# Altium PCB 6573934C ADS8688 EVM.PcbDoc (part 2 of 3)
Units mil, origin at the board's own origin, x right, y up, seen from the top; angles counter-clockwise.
Board outline 4100 x 2700 mil, 6 copper layers (L1_Analog, L2_GND, L3_AnalogPower, L4_DigPower, L5_GND, L6_Digital), stack 58.4 mil thick; 282 components, 187 nets, 719 pads, 318 vias.
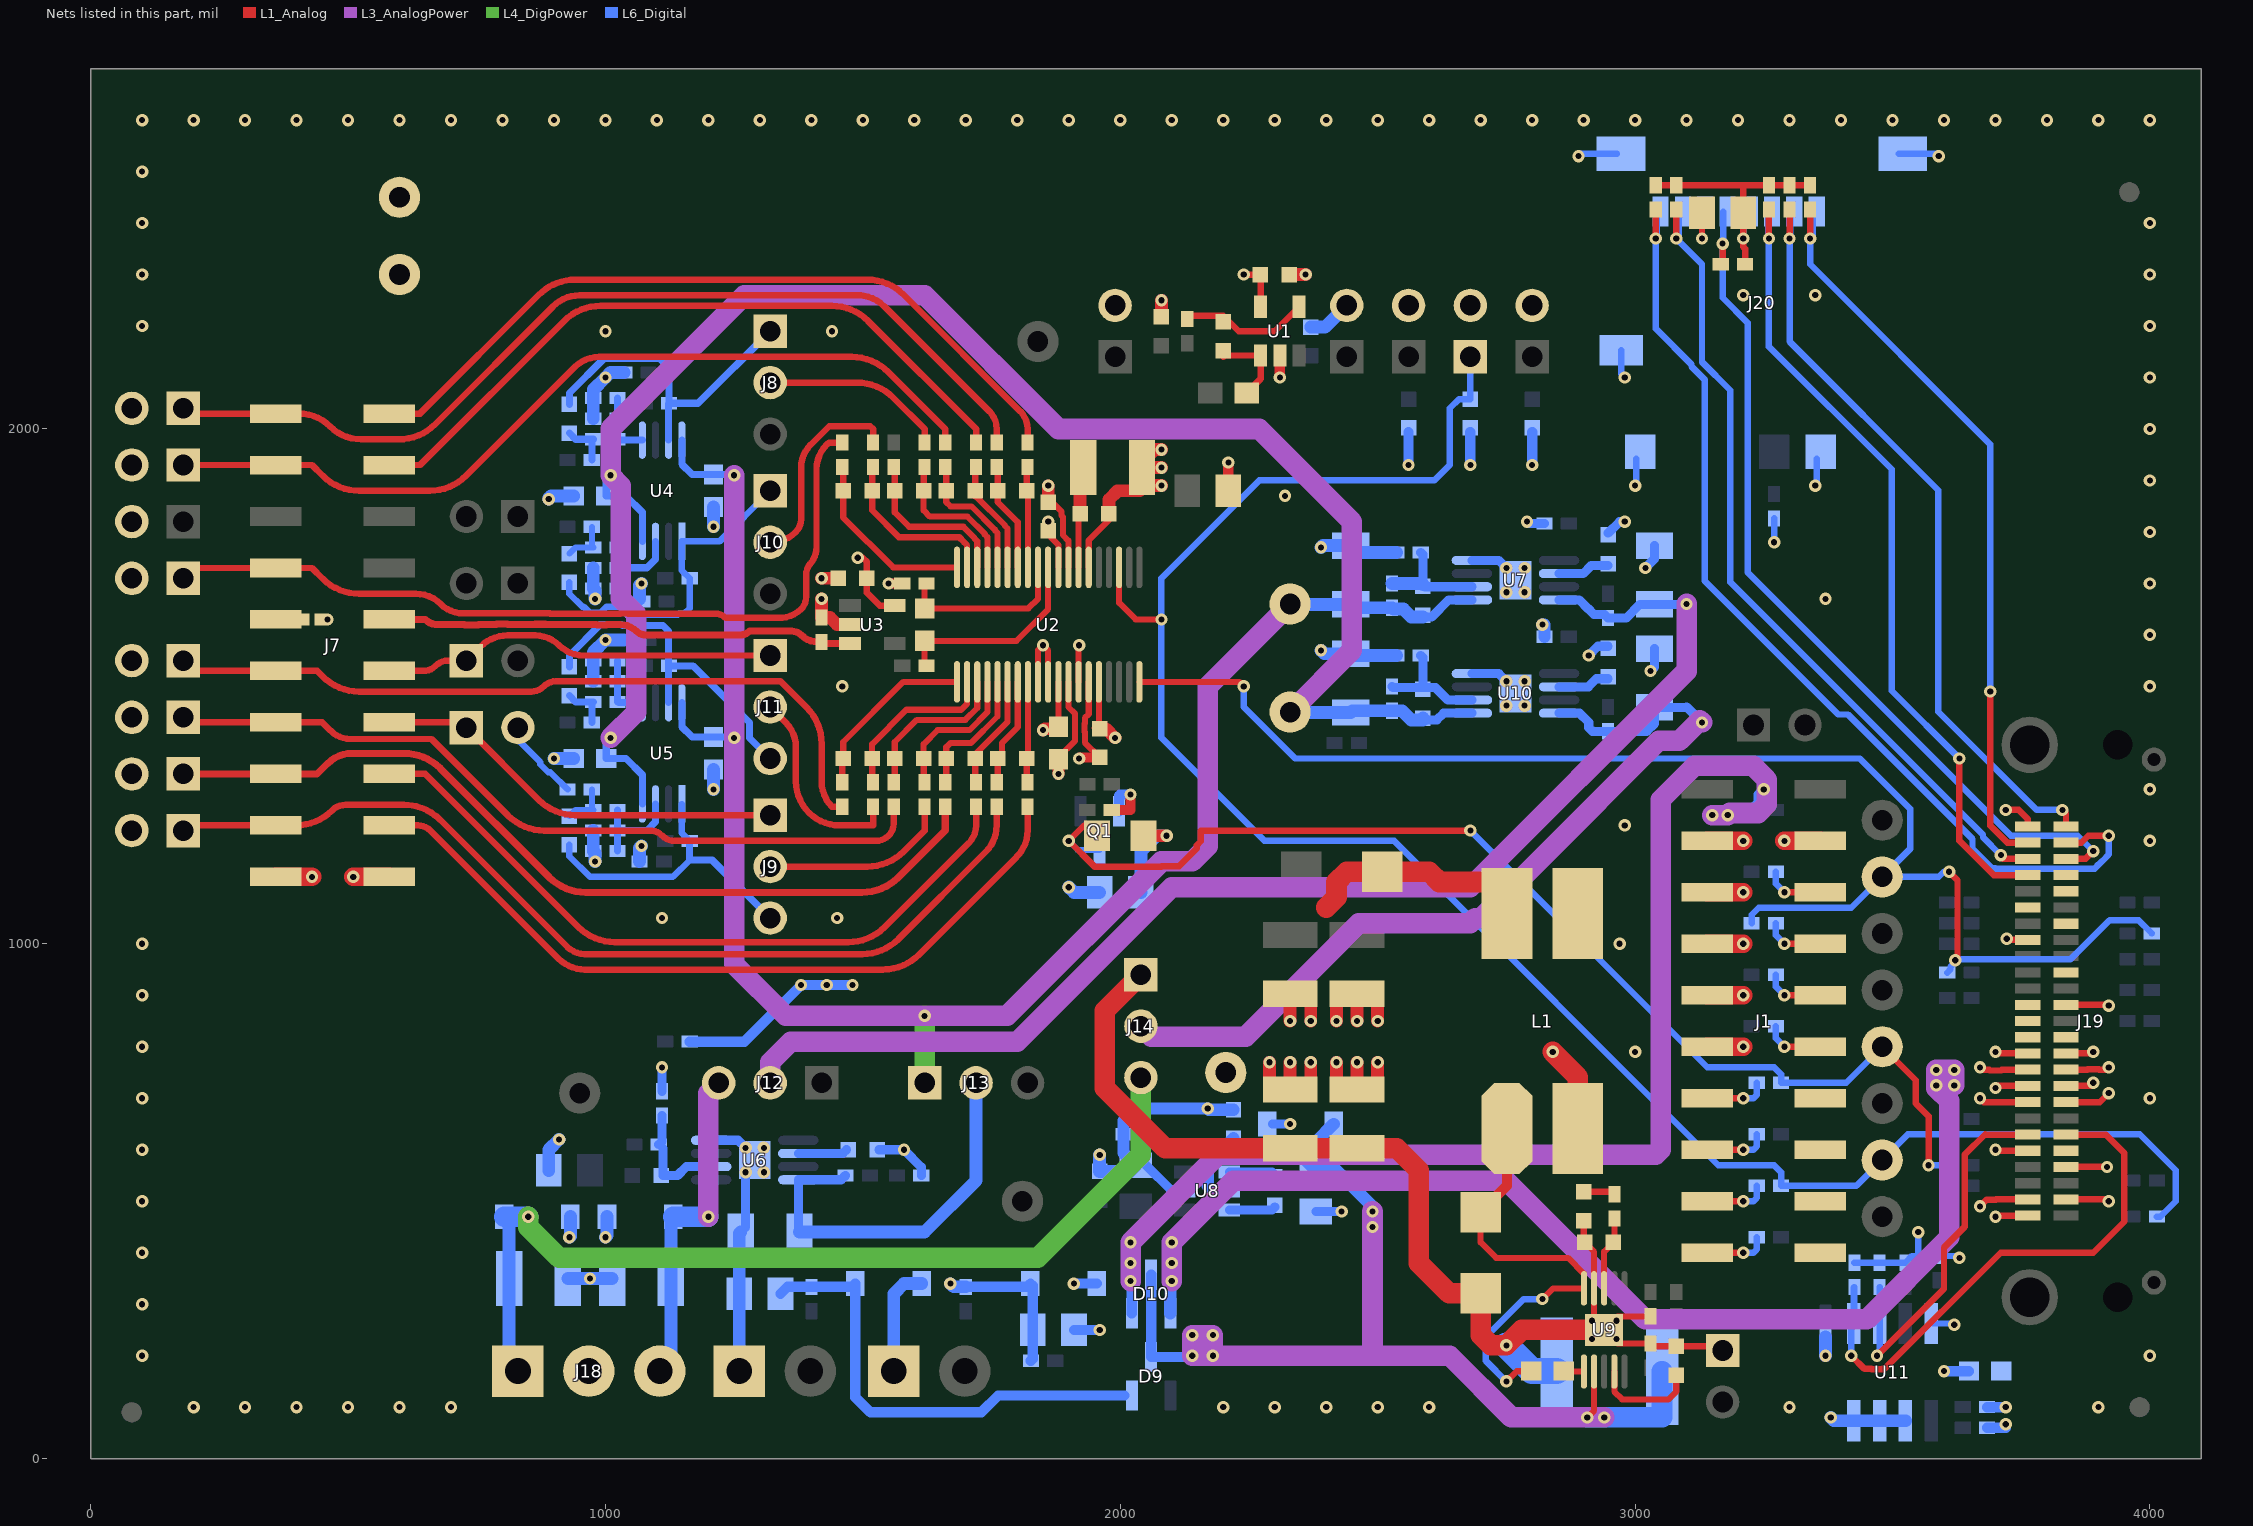
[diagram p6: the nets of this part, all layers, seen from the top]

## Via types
v1: diameter 24, hole 12, L1_Analog to L6_Digital, tented both sides, 318 vias

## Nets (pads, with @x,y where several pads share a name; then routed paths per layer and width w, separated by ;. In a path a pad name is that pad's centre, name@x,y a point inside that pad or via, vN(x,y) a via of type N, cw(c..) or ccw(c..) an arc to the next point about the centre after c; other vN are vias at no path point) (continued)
A1-: J7.7 J16.1 R40.1 | length 1605.9
  L1_Analog w12.52: J16.1@180,1710 200,1730 J7.7@360,1730 430,1730 450.71,1709.29 ccw(c521.42,1780) 521.42,1680 631.72,1680 cw(c631.72,1611.72) 680,1660 ccw(c723.99,1703.99) 723.99,1641.78 779.48,1641.78 779.55,1641.85 869.93,1641.85 ; 869.93,1641.78 892.02,1641.78 892.78,1641.02 1022.22,1641.02 1022.63,1641.44 1029.2,1641.44 1029.2,1641.58 1043.84,1641.58 1044.4,1641.02 1215.25,1641.02 cw(c1215.25,1618.39) 1220.69,1640.36 cw(c1215.25,1618.39) 1231.26,1634.39 ccw(c1238.44,1659.46) 1238.44,1633.39 1339.89,1633.39 ccw(c1339.89,1690.11) 1343.5,1633.5 ccw(c1339.89,1690.11) 1380,1650 ccw(c1355.86,1674.14) 1390,1674.14 1390,1717.09 cw(c1422.82,1717.09) 1396.07,1736.11 cw(c1422.82,1717.09) 1399.61,1740.29 ccw(c1358.79,1771.21) 1410,1771.21 1410,1921.72 cw(c1478.28,1921.72) 1430,1970 cw(c1438.74,1961.26) 1438.74,1973.62 R40.1@1460,1973.62
A2+: J7.12 J11.1 J30.1 | length 782.2
  L1_Analog w12.52: J7.12@580,1530 645.86,1530 ccw(c645.86,1564.14) 669.98,1539.98 ; 670.02,1540.02 cw(c694.14,1515.86) 694.14,1550 J30.1@730,1550 757.04,1577.04 cw(c810,1524.08) 810,1598.98 863.46,1598.98 cw(c863.46,1532.44) 910.51,1579.49 ccw(c957.56,1626.54) 957.56,1560 J11.1@1320,1560 ; J30.1@723.39,1536.61 J30.1@730,1530
A2-: J7.11 J26.1 R41.2 | length 1483.7
  L1_Analog w12.52: J26.1@180,1550 200,1530 J7.11@360,1530 440,1530 450.71,1519.29 ccw(c521.42,1590) 521.42,1490 855.86,1490 ccw(c855.86,1524.14) 880,1500 cw(c904.14,1475.86) 904.14,1510 1340,1510 1390.71,1459.29 cw(c1320,1388.58) 1420,1388.58 1420,1314.66 ccw(c1488.28,1314.66) 1440,1266.38 R41.2@1460,1266.38
A3+: J7.14 J9.1 J15.1 | length 810.3
  L1_Analog w12.52: J7.14@580,1430 720,1430 J15.1@730,1420 870.71,1279.29 ccw(c941.42,1350) 941.42,1250 J9.1@1320,1250
A3-: J7.13 J27.1 R35.2 | length 1521.5
  L1_Analog w12.52: J27.1@180,1440 190,1430 J7.13@360,1430 450,1430 466.07,1413.93 ccw(c504.86,1452.72) 504.86,1397.87 662.13,1397.87 810.71,1249.29 ccw(c881.42,1320) 881.42,1220 1085.86,1220 cw(c1085.86,1185.86) 1109.98,1210.02 ; 1110.02,1209.98 ccw(c1134.14,1234.14) 1134.14,1200 1525.86,1200 ccw(c1525.86,1234.14) 1550,1210 ccw(c1525.86,1234.14) 1560,1234.14 R35.2@1560,1266.38
A4+: J7.16 R28.2 | length 1406.6
  L1_Analog w12.52: J7.16@580,1330 650,1330 947.32,1032.68 ccw(c1018.04,1103.39) 1018.04,1003.39 1471.96,1003.39 ccw(c1471.96,1103.39) 1517.11,1014.16 ccw(c1471.96,1103.39) 1542.68,1032.68 1705.86,1195.86 ccw(c1671.72,1230) 1720,1230 R28.2@1720,1266.38
A4-: J7.15 J28.1 R30.2 | length 1688.6
  L1_Analog w13.78: J28.1@180,1330 J7.15@360,1330 440,1330 460,1350 cw(c508.28,1301.72) 508.28,1370 608.58,1370 cw(c608.58,1270) 679.29,1340.71 890.71,1129.29 ccw(c961.42,1200) 961.42,1100 1498.58,1100 ccw(c1498.58,1200) 1569.29,1129.29 1660,1220 R30.2@1660,1266.38
A5+: J7.18 R24.2 | length 1519.8
  L1_Analog w12.52: J7.18@580,1230 635.86,1230 cw(c635.86,1195.86) 660,1220 908.79,971.21 ccw(c960,1022.43) 960,950 1538.58,950 ccw(c1538.58,1050) 1550.74,950.74 ccw(c1538.58,1050) 1609.29,979.29 1798.79,1168.79 ccw(c1747.57,1220) 1820,1220 R24.2@1820,1266.38
A5-: J7.17 J29.1 R26.2 | length 1858.7
  L1_Analog w12.52: J29.1@180,1220 190,1230 J7.17@360,1230 398.58,1230 ccw(c398.58,1330) 469.29,1259.29 cw(c495.15,1233.43) 495.15,1270 608.58,1270 cw(c608.58,1170) 633.04,1266.96 cw(c608.58,1170) 679.29,1240.71 925.86,994.14 ccw(c960,1028.28) 960,980 1498.58,980 ccw(c1498.58,1080) 1569.29,1009.29 1738.79,1178.79 ccw(c1687.58,1230) 1760,1230 R26.2@1760,1266.38
A6+: J7.2 R23.1 | length 1495.2
  L1_Analog w12.52: J7.2@580,2030 640,2030 870.71,2260.71 cw(c941.42,2190) 897.83,2280 cw(c941.42,2190) 941.42,2290 1508.58,2290 cw(c1508.58,2190) 1579.29,2260.71 1805.86,2034.14 cw(c1771.72,2000) 1820,2000 R23.1@1820,1973.62
A6-: J7.1 J24.1 R25.1 | length 1847.4
  L1_Analog w12.52: J24.1@180,2040 190,2030 J7.1@360,2030 404.64,2030 cw(c404.64,1944.64) 464.96,2005.04 cw(c404.64,1944.64) 465,2005 ccw(c525.36,2065.36) 465.04,2004.96 ccw(c525.36,2065.36) 525.36,1980 598.58,1980 ccw(c598.58,2080) 669.29,2009.29 898.11,2238.11 ; 898.13,2238.13 cw(c950,2186.23) 950,2259.61 968.77,2259.61 969.36,2260.19 990.63,2260.19 990.63,2260.01 997.01,2260.01 997.41,2259.61 1227.26,2259.61 1432.59,2259.61 1432.99,2260.01 1439.37,2260.01 1439.37,2260.19 1460.64,2260.19 1461.23,2259.61 1490,2259.61 cw(c1490,2186.23) 1501.26,2258.74 cw(c1490,2186.23) 1541.89,2238.11 1745.86,2034.14 cw(c1711.72,2000) 1760,2000 R25.1@1760,1973.62
A7+: J7.4 R27.1 | length 1384.9
  L1_Analog w12.52: J7.4@580,1930 640,1930 919.92,2209.92 cw(c990.63,2139.21) 990.63,2239.21 1439.37,2239.21 cw(c1439.37,2139.21) 1510.08,2209.92 1720,2000 R27.1@1720,1973.62
A7-: J7.3 J23.1 R29.1 | length 1676.9
  L1_Analog w12.52: J23.1@180,1930 J7.3@360,1930 430,1930 450.71,1909.29 ccw(c521.42,1980) 521.42,1880 658.58,1880 ccw(c658.58,1980) 729.29,1909.29 940,2120 cw(c988.28,2071.72) 988.28,2140 1478.58,2140 cw(c1478.58,2040) 1549.29,2110.71 1660,2000 R29.1@1660,1973.62
A\L\M\: D1.1 Q1.3 R2.1 R86.2 TP8.1 | length 2325.3
  L1_Analog w11.81: v1(1900,1200) 1930,1230 D1.1@1955,1230
  L1_Analog w12.52: v1(1900,1200) 1950,1150 2080,1150 2080.99,1150.99 2114.44,1150.99 2149.01,1185.56 2149.01,1191.34 2156.63,1198.97 2156.63,1220 v1(2680,1220) ; TP8.1@3480,800 3545,735 3545,690 3570,665 v1(3570,570)
  L6_Digital w11.81: v1(1900,1200) 1917.4,1182.6 Q1.3@1960,1182.6
  L6_Digital w12.52: v1(2680,1220) 3140,760 3270,760 3283.62,746.38 R2.1@3283.62,730 3410,730 TP8.1@3480,800 ; v1(3570,570) R86.2@3606.38,570
AUX+: J7.10 R11.2 U3.3 | length 914.9
  L1_Analog w13.78: J7.10@580,1630 650,1630 ; 650.02,1629.98 ccw(c674.14,1654.14) 674.14,1620 725.93,1620 726.69,1619.24 746.54,1619.24 746.54,1619.59 753.11,1619.59 753.52,1620 787.43,1620 788.18,1620.76 788.26,1620.83 795.3,1620.83 810,1620.83 810,1620.41 816.57,1620.41 816.98,1620 851.29,1620 856.48,1620 856.89,1620.41 863.46,1620.41 863.46,1620.76 883.31,1620.76 884.07,1620 983.02,1620 983.43,1619.59 990,1619.59 ; 990,1619.55 1001.71,1619.55 1002.16,1620 1029.2,1620 cw(c1029.2,1576.45) 1060,1607.24 ccw(c1077.49,1624.73) 1077.49,1600 1262.51,1600 ccw(c1262.51,1624.73) 1280,1607.24 1362.51,1607.24 cw(c1362.51,1582.51) 1362.76,1607.24 cw(c1362.51,1582.51) 1380,1600 ccw(c1412.89,1632.89) 1412.89,1586.38 R11.2@1420,1586.38 1423.38,1583 U3.3@1475,1583
AUX-: J7.9 NT1.2 | length 49.9
  L1_Analog w12.52: J7.9@360,1630 J7.9@409.87,1630
AVDD: C1.1 C2.1 C10.2 C63.1 R77.1 TP16.1 U1.5 U2.9 U2.30 U3.5 | length 818.2
  L1_Analog w11.81: v1(1860,1820) C10.2@1860,1802 1860,1795 1869.09,1785.91 1869.09,1785.58 1879.69,1774.99 U2.9@1879.69,1731.22 ; U2.30@1879.69,1508.78 1879.69,1421.81 C63.1@1880,1421.5
  L1_Analog w12.52: v1(1490,1750) 1500,1750 1508,1742 C1.1@1508,1710 1508,1682 1533,1657 U3.5@1562,1657 ; v1(2240,2300) C2.1@2272,2300 2272.6,2299.4 U1.5@2272.6,2237.24
  L1_Analog w24: v1(1850,1415) 1853,1418 C63.1@1880,1418
  L6_Digital w20: R77.1@1163.62,810 1270,810 v1(1380,920) v1(1430,920) v1(1480,920)
C\S\: R7.1 R90.1 R103.2 TP7.1 U2.38 | length 2849.4
  L1_Analog w11.81: U2.38@2037.17,1508.78 2231.22,1508.78 v1(2240,1500)
  L1_Analog w12.52: v1(3610,1140) 3626.27,1123.73 3626.27,969.27 3625.32,968.32 v1@3622.27,968.32
  L3_AnalogPower w12.52: v1(3621.87,967.92) 3621.87,966.05 v1@3622.27,965.65 ; v1@3622.27,968.32 v1@3622.27,965.65 ; v1@3622.27,965.65 3622.27,965.27 3622.65,965.27 v1@3622.27,965.65
  L6_Digital w12.52: v1(2240,1500) 2240,1460 2340,1360 3436.56,1360 3534.13,1262.42 3534.13,1184.13 TP7.1@3480,1130 ; R7.1@3226.38,1040 3226.38,1056.38 3240,1070 3420,1070 TP7.1@3480,1130 ; R103.2@3606.38,944 3612.69,950.31 3612.69,955.31 3625.29,967.92 v1(3621.87,967.92) ; v1(3610,1140) 3600,1140 3590,1130 TP7.1@3480,1130 ; v1@3632.02,969.94 3845.72,969.94 3921.62,1045.84 3934.67,1045.84 3934.77,1045.95 3977.98,1045.95 4003.62,1020.3 R90.1@4003.62,1020
DAISY: J4.1 R8.1 R15.2 R89.1 TP3.1 U2.3 | length 3890.2
  L1_Analog w11.81: U2.3@1997.8,1731.22 1997.8,1662.2 2030,1630 v1(2080,1630)
  L6_Digital w12.52: J4.1@2680,2140 R15.2@2680,2058 2658,2058 2640,2040 2640,1930 2610,1900 2270,1900 2080,1710 v1(2080,1630) 2080,1400 2280,1200 2531.81,1200 3161.81,570 3270,570 3283.62,556.38 3283.62,530.3 R8.1@3283.62,530 3430,530 TP3.1@3480,580 3530,630 3980,630 4050,560 4050,500 4020,470 R89.1@4013.62,470
DVDD: C5.1 C61.1 C62.1 C64.1 D7.1 J20.4 R12.2 R13.1 R15.1 R18.1 R78.2 R79.2 R80.2 R81.2 R82.2 R83.2 R84.2 R85.2 R94.1 R95.1 R96.1 R102.1 R106.2 R108.2 TP17.1 U2.34 U11.8 | length 1617.4
  L1_Analog w11.81: C5.1@1950.43,1419.57 1958.43,1419.57 U2.34@1958.43,1508.78
  L1_Analog w12.52: R79.2@3040,2473.62 3210,2473.62 ; R81.2@3213.62,2320 3213.62,2350 3210,2353.62 v1(3210,2370) 3210,2473.62 ; R84.2@3340,2473.62 3210,2473.62
  L1_Analog w24: C5.1@1960,1418 1972,1418 v1(1990,1400)
  L6_Digital w12.52: v1(3210,2370) J20.4@3210,2425.12 ; v1(3270,1780) R85.2@3270,1826.38 ; R94.1@3426,380.62 R96.1@3525,380.62 3538,393.62 3550,393.62 v1(3550,440) ; U11.8@3575,262.5 3617.5,262.5 v1(3620,260) ; J20.4@3210,2425.12 3212.76,2422.36 3214.88,2422.36 3212.13,2425.12 J20.4@3210,2425.12
  L6_Digital w20: R106.2@1700,333.62 1819.15,333.62 D7.1@1825.53,340 1830,335.53 C61.1@1830,250 1830,193.62 R78.2@1826.38,190 ; v1(2560,1930) R18.1@2560,1994.22 ; v1(2680,1930) R15.1@2680,1994.22 ; v1(2800,1930) R13.1@2800,1994.22 ; v1(3600,170) C64.1@3648.5,170 ; R102.1@3683.62,100 v1(3720,100)
  L6_Digital w24: v1(1670,340) 1676.38,333.62 R106.2@1700,333.62
  L6_Digital w25: v1(1900,1110) 1910,1100 R12.2@1960,1100 ; v1(3370,200) R108.2@3370,236.38
EVM_ID_SCL: J19.12 R95.2 U11.6 | length 735.6
  L1_Analog w12.52: v1(3470,200) 3600,330 3600,410 3640,450 3640,590 3680,630 3680.47,629.53 J19.12@3762.99,629.53
  L6_Digital w12.52: v1(3470,200) 3475,205 U11.6@3475,262.5 R95.2@3475,333.38
EVM_ID_SDA: J19.11 R94.2 U11.5 | length 1119.5
  L1_Analog w12.52: v1(3420,200) 3445.78,174.22 3458.82,174.22 3459.17,173.87 3480.83,173.87 3481.18,174.22 3484.22,174.22 3710,400 3890,400 3950,460 3950,593.67 3914.15,629.53 J19.11@3837.01,629.53
  L6_Digital w12.52: v1(3420,200) U11.5@3420,257.5 ; U11.5@3425,262.5 3425,332.38 R94.2@3426,333.38 U11.5@3426,263.5
EVMSDCLK: J19.45 J20.5 R81.1 | length 1720.2
  L1_Analog w12.52: R81.1@3166.38,2320 3170,2320 v1(3170,2360) ; J19.45@3837.01,1164.96 3874.96,1164.96 v1(3890,1180)
  L6_Digital w12.52: J20.5@3171.58,2422.36 3171.58,2371.57 3170,2370 v1(3170,2360) 3170,2255 3218.46,2206.54 3218.46,1721.54 3730,1210 3860,1210 v1(3890,1180)
EVMSDCMD: J19.44 J20.3 R82.1 | length 1583.3
  L1_Analog w12.52: v1(3260,2370) R82.1@3260,2416.38 ; v1(3630,1360) 3630,1200 3696.54,1133.46 J19.44@3762.99,1133.46
  L6_Digital w12.52: J20.3@3258.19,2422.36 3258.19,2371.81 v1(3260,2370) 3260,2160 3498.46,1921.54 3498.46,1491.54 v1(3630,1360)
EVMSDDATA0: J19.46 J20.7 R80.1 | length 1627.2
  L1_Analog w12.52: v1(3080,2370) R80.1@3080,2426.38 ; v1(3710.45,1172.31) 3710.45,1170.45 3710,1170 3715.04,1164.96 J19.46@3762.99,1164.96
  L6_Digital w12.52: J20.7@3084.96,2422.36 3084.96,2374.96 v1(3080,2370) 3130,2320 3130,2130 3185,2075 3185,1702.68 3675.79,1211.89 3675.79,1206.97 v1(3710.45,1172.31)
EVMSDDATA1: J19.47 J20.8 R79.1 | length 1978.8
  L1_Analog w12.52: v1(3040,2370) R79.1@3040,2426.38 ; J19.47@3837.01,1196.46 3866.46,1196.46 3880,1210 v1(3920,1210)
  L6_Digital w12.52: J20.8@3041.65,2422.36 3041.65,2371.65 v1(3040,2370) 3040,2195 3109.61,2125.39 3109.61,2121.55 3135,2096.16 3135,1705 3394.61,1445.39 3413.45,1445.39 3655.39,1203.45 3655.39,1186.55 3654.42,1185.58 3693.47,1146.53 3699.27,1146.53 3699.63,1146.17 3892.63,1146.17 3900.32,1153.87 3900.82,1153.87 3916.13,1169.18 3916.13,1169.68 3920,1173.54 v1(3920,1210)
EVMSDDATA2: J19.48 J20.1 R84.1 | length 1482.8
  L1_Analog w12.52: v1(3340,2370) R84.1@3340,2426.38 ; v1(3690,1490) 3690,1229.72 3723.26,1196.46 J19.48@3762.99,1196.46
  L6_Digital w12.52: J20.1@3344.8,2422.36 3344.8,2374.8 v1(3340,2370) 3340,2320 3690,1970 v1(3690,1490)
EVMSDDATA3: J19.49 J20.2 R83.1 | length 1493.1
  L1_Analog w12.52: v1(3300,2370) R83.1@3300,2416.38 ; v1(3830,1260) 3837.01,1252.99 J19.49@3837.01,1227.95
  L6_Digital w12.52: J20.2@3301.5,2422.36 3301.5,2371.5 v1(3300,2370) 3300,2170 3589.02,1880.98 3589.02,1450.98 3780,1260 v1(3830,1260)
EXT_5V: C55.1 D5.1 D9.2 R69.2 | length 922.5
  L6_Digital w20: C55.1@1340,320 1353.62,333.62 R69.2@1400,333.62 1479.15,333.62 D5.1@1485.53,340 1485.53,119.19 1514.72,90 1730,90 1762.6,122.6 2007.8,122.6
EXT_HVDD: C59.2 D6.1 J12.3 J18.3 | length 647.2
  L3_AnalogPower w40: v1(1200,470) 1200,710 J12.3@1220,730
  L6_Digital w25: J18.3@1105.59,170 1127.09,191.5 1127.09,465.07 D6.1@1132.01,470
  L6_Digital w40: D6.1@1132.01,470 v1(1200,470)
EXT_HVSS: C60.1 D8.2 J14.3 J18.1 | length 1825.7
  L4_DigPower w40: v1(850,470) 850,450 910,390 1840,390 2040,590 J14.3@2040,740
  L6_Digital w25: D8.2@803.14,470 812.91,460.22 812.91,187.09 J18.1@830,170
  L6_Digital w40: D8.2@803.14,470 v1(850,470)
GND: C1.2 C2.2 C3.2 C5.2 C6.2 C7.2 C8.1 C9.1 C10.1 C16.1 C23.2 C24.1 C25.2 C26.2 C29.2 C30.2 C31.2 C32.2 C33.2 C34.2 C35.2 C36.2 C37.2 C40.2 C41.2 C43.2 C44.2 C46.2 C47.2 C49.1 C50.1 C53.2 C54.2 C55.2 C58.2 C59.1 C60.2 C61.2 C62.2 C63.2 C64.2 D3.2 D5.2 D6.2 D7.2 D8.1 J1.4 J2.2 J3.2 J4.2 J5.2 J6.2 J7.19 J7.20 J16.2 J18.2 J19.2 J19.4 J19.10 J19.16 J19.50 J20.0 J20.6 J22.2 J23.2 J24.2 J26.2 J27.2 J28.2 J29.2 J32.1 J33.1 L1.2 L1.3 NT1.1 Q1.2 R11.1 R14.1 R20.1 R21.1 R22.1 R36.1 R44.1 R48.2 R52.2 R57.2 R59.1 R62.2 R64.1 R65.2 R73.1 R74.1 R75.1 R76.1 R97.2 R104.2 TP11.1 U1.2 U2.6 U2.8 U2.28 U2.29 U2.31 U2.32 U2.33 U3.2 U6.4 U6.9 U7.4 U7.9 U8.2 U10.4 U10.9 U11.2 U11.3 U11.4 | length 7074.5
  L1_Analog w11.81: U2.28@1840.32,1508.78 1840.32,1570.32 v1(1850,1580) 1860,1570 U2.29@1860,1508.78 ; C10.1@1860,1858 1863,1855 1870.68,1855 1885.78,1839.9 1885.78,1832.22 1888.78,1829.22 1888.78,1793.73 1899.37,1783.14 U2.8@1899.37,1731.22 ; C63.2@1880,1362 1912.48,1394.48 1912.48,1446.89 1899.37,1460 U2.31@1899.37,1508.78 ; U2.32@1919.06,1508.78 1919.06,1579.06 v1(1920,1580) ; U2.33@1938.74,1508.78 1938.74,1446.23 1931.22,1438.71 1931.22,1428.21 1930.74,1427.73 1930.74,1411.42 1931.22,1410.94 1931.22,1390.78 C5.2@1960,1362 ; U2.6@1938.74,1731.22 1938.74,1783.74 1978,1823 C9.1@1978,1835
  L1_Analog w12.52: v1(3130,2370) C62.2@3130,2420 ; v1(3670,490) 3683.24,503.24 3701.09,503.24 3701.39,503.54 J19.4@3762.99,503.54 ; v1(3670,700) 3677.48,692.52 J19.16@3762.99,692.52 ; v1(3700,470) 3702.05,472.05 J19.2@3762.99,472.05 ; v1(3700,600) 3701.97,598.03 J19.10@3762.99,598.03 ; v1(3720,1260) 3745.47,1260 3762.99,1242.48 J19.50@3762.99,1227.95
  L1_Analog w20: v1(1550,1700) R14.1@1576.38,1700 ; v1(1920,1360) 1922,1362 C5.2@1960,1362 ; R20.1@1983.62,1260 2020,1260 v1(2020,1290) ; C7.2@2210,1880 v1(2210,1935) ; v1(2310,2100) U1.2@2310,2142.76
  L1_Analog w24: C10.1@1860,1858 v1(1860,1890) ; v1(1880,1330) C63.2@1880,1358.5 C63.2@1880,1362
  L1_Analog w25: v1(1420,1670) R11.1@1420,1633.62 1436.07,1633.62 1449.69,1620 U3.2@1475,1620 ; v1(1420,1710) C1.2@1452,1710 ; C9.1@1978,1835 1978,1863 1995,1880 2037.09,1880 C8.1@2042.09,1885 ; v1(2080,1890) 2047.09,1890 C8.1@2042.09,1885 ; v1(2080,1925) C8.1@2042.09,1925 ; v1(2080,1960) 2067.09,1960 2037.09,1930 C8.1@2042.09,1925 ; C6.2@2080,2218 v1(2080,2250) ; v1(2290,770) 2290,717.09 C50.1@2330,717.09 ; C2.2@2328,2300 v1(2360,2300) ; v1(2330,770) C50.1@2330,717.09 ; v1(2330,850) C35.2@2330,902.91 2370,902.91 v1(2370,850) ; v1(2370,770) 2370,717.09 C50.1@2330,717.09 ; v1(2420,770) 2420,717.09 C49.1@2460,717.09 ; v1(2420,850) 2420,902.91 C32.2@2460,902.91 ; v1(2460,770) C49.1@2460,717.09 ; v1(2460,850) C32.2@2460,902.91 ; v1(2500,770) 2500,717.09 C49.1@2460,717.09 ; v1(2500,850) 2500,902.91 C32.2@2460,902.91 ; C8.1@2042.09,1885 C8.1@2042.09,1925
  L1_Analog w36: J7.19@360,1130 v1(430,1130) ; v1(510,1130) J7.20@580,1130 ; v1(3290,1200) J1.4@3360,1200
  L1_Analog w40: v1(2840,790) 2888.9,741.1 L1.2@2888.9,641.34
  L6_Digital w12.52: v1(2890,2530) 2894.57,2534.57 J20.0@2964.88,2534.57 ; J20.0@2972.76,2152.68 2972.76,2107.24 v1(2980,2100) ; v1(3000,1890) 3002.28,1892.28 J20.0@3002.28,1942.05 ; J20.6@3128.27,2422.36 3130,2420.63 v1(3130,2370) ; v1(3350,1890) 3352.68,1892.68 J20.0@3352.68,1942.05 ; J20.0@3512.13,2534.57 3585.43,2534.57 v1(3590,2530) ; R104.2@3590,393.62 3626.38,393.62 v1(3630,390)
  L6_Digital w17.72: R57.2@1110,713.62 v1(1110,760) ; U6.4@1205.35,618.39 1257.52,618.39 v1(1272.28,603.62) ; C34.2@1272.28,449.37 v1(1272.28,556.38) ; C40.2@1531.5,600 v1(1580,600) 1613.62,566.38 R62.2@1613.62,550 ; C43.2@2050,570 2100,520 U8.2@2125,520 ; D3.2@2295.53,650 v1(2330,650) ; C47.2@2380,480 v1(2430,480) ; U10.4@2683.07,1524.76 2735.24,1524.76 v1(2750,1510) ; U7.4@2683.07,1744.76 2735.24,1744.76 v1(2750,1730) ; v1(2790,1820) 2793.62,1816.38 R64.1@2824.09,1816.38 ; v1(2910,1560) 2927.87,1577.87 C58.2@2947.72,1577.87 ; C41.2@2947.72,1797.87 2969.84,1820 v1(2980,1820) ; v1(3020,1730) 3037.72,1747.72 C37.2@3037.72,1773.46 ; v1(3030,1530) 3037.72,1537.72 C54.2@3037.72,1573.46
  L6_Digital w20: C61.2@1910,250 v1(1960,250) ; v1(1910,340) D7.2@1954.47,340 ; Q1.2@1997.4,1257.4 1997.4,1287.4 2000,1290 v1(2020,1290) ; R97.2@3683.62,60 3720,60 v1(3720,66.87)
  L6_Digital w24: C43.2@2030,570 2006.38,593.62 2006.38,656.38 2030,680 v1(2170,680) 2172,678 C46.2@2220,678 ; v1(2820,1620) 2824.09,1620 R75.1@2824.09,1596.38
  L6_Digital w25: C33.2@890,560 890,600 v1(910,620) ; v1(890,1863.77) 890,1865.96 894.04,1870 C24.1@938.5,1870 ; v1(900,1360) C30.2@938.5,1360 ; C60.2@927.09,350 v1(970,350) C59.1@1012.91,350 ; v1(930,430) 932.08,432.08 D8.1@932.07,470 ; C29.2@976.38,1220 R74.1@976.38,1180 980,1176.38 v1(980,1160) ; C31.2@976.38,1510 R21.1@976.38,1550 976.38,1566.38 v1(1000,1590) R52.2@1036.38,1590 ; C23.2@976.38,1730 R22.1@976.38,1690 980,1686.38 v1(980,1670) ; C25.2@976.38,2020 R76.1@976.38,2060 976.38,2076.38 v1(1000,2100) 1010,2110 R44.1@1036.38,2110 ; v1(1000,430) 1003.08,433.08 D6.2@1003.08,470 ; R48.2@1066.38,1160 1066.38,1186.38 v1(1070,1190) ; R36.1@1066.38,1670 1066.38,1696.38 v1(1070,1700) ; v1(1210,1300) C26.2@1210,1338.5 ; v1(1210,1810) C16.1@1210,1848.5 ; J32.1@1260,170 C55.2@1260,320 1260,437.09 C34.2@1262.91,440 ; J33.1@1560,170 1560,320 1580,340 D5.2@1614.47,340 ; v1(1960,590) C44.2@1960,558 2018,558 C43.2@2030,570 ; C3.2@2370,2198 2398,2198 J5.2@2440,2240 ; v1(2390,1570) 2396.54,1563.46 C53.2@2447.72,1563.46 ; v1(2390,1770) 2393.46,1773.46 C36.2@2447.72,1773.46 2461.18,1760 R59.1@2536.38,1760 ; C53.2@2451.18,1560 R73.1@2536.38,1560 ; v1(3380,80) 3386.5,73.5 U11.2@3525,73.5
  other v1: 200,100 300,100 400,100 500,100 600,100 700,100 2200,100 2300,100 2400,100 2500,100 2600,100 3300,100 3900,100 100,200 4000,200 100,300 100,400 100,500 1307.72,556.38 100,600 1307.72,603.62 100,700 4000,700 3000,790 100,800 100,900 100,1000 2970,1000 1110,1050 1450,1050 4000,1200 2980,1230 4000,1300 2750,1462.76 2785.43,1462.76 1460,1500 4000,1500 2785.43,1510 4000,1600 460,1630 3370,1670 2750,1682.76 2785.43,1682.76 4000,1700 2785.43,1730 4000,1800 2320,1870 4000,1900 4000,2000 4000,2100 1000,2190 1440,2190 100,2200 4000,2200 3210,2260 3350,2260 100,2300 4000,2300 100,2400 4000,2400 100,2500 100,2600 200,2600 300,2600 400,2600 500,2600 600,2600 700,2600 800,2600 900,2600 1000,2600 1100,2600 1200,2600 1300,2600 1400,2600 1500,2600 1600,2600 1700,2600 1800,2600 1900,2600 2000,2600 2100,2600 2200,2600 2300,2600 2400,2600 2500,2600 2600,2600 2700,2600 2800,2600 2900,2600 3000,2600 3100,2600 3200,2600 3300,2600 3400,2600 3500,2600 3600,2600 3700,2600 3800,2600 3900,2600 4000,2600
HVDD: C16.2 C26.1 C36.1 C39.1 J13.1 R56.2 TP13.1 U4.8 U5.8 U7.1 | length 3406.2
  L3_AnalogPower w40: v1(1250,1910) v1(1250,1400) 1250,960 1350,860 v1(1620,860) 1780,860 2080,1160 2140,1160 2170,1190 2170,1500 TP13.1@2330,1660
  L4_DigPower w40: J13.1@1620,730 v1(1620,860)
  L6_Digital w13.78: U5.8@1148.39,1468.43 1148.39,1421.61 1168.5,1401.5 C26.1@1210,1401.5 1248.5,1401.5 v1(1250,1400) ; U4.8@1148.39,1978.43 1148.39,1931.61 1168.5,1911.5 C16.2@1210,1911.5 1248.5,1911.5 v1(1250,1910)
  L6_Digital w17.72: C39.1@2587.72,1634.88 2604.88,1634.88 2637.99,1667.99 U7.1@2683.07,1667.99
  L6_Digital w25: TP13.1@2330,1660 ccw(c2331.71,1661.71) 2331.71,1659.29 C36.1@2447.72,1659.29 2454.25,1652.76 R56.2@2527.72,1652.76 2530.47,1650 2550,1650 2565.12,1634.88 C39.1@2587.72,1634.88
HVSS: C24.2 C30.1 C53.1 C56.1 R71.2 TP15.1 U4.4 U5.4 U10.1 | length 3529.2
  L3_AnalogPower w40: v1(1010,1400) 1060,1450 1060,1640 1030,1670 1030,1890 v1(1010,1910) 1010,2000 1270,2260 1620,2260 1880,2000 2270,2000 2450,1820 2450,1570 TP15.1@2330,1450
  L6_Digital w13.78: v1(1010,1400) 1001.5,1391.5 C30.1@1001.5,1360 1040,1360 1071.61,1328.39 U5.4@1071.61,1271.57 ; v1(1010,1910) 1001.5,1901.5 C24.2@1001.5,1870 1040,1870 1071.61,1838.39 U4.4@1071.61,1781.57
  L6_Digital w17.72: C56.1@2587.72,1434.88 2614.88,1434.88 2627.99,1447.99 U10.1@2683.07,1447.99
  L6_Digital w25: TP15.1@2330,1450 ccw(c2331.71,1451.71) 2331.71,1449.29 C53.1@2447.72,1449.29 2451.18,1452.76 2547.24,1452.76 2565.12,1434.88 2587.72,1434.88 C56.1@2587.72,1438.38
J1-3: J1.3 | length 70
  L1_Analog w36: J1.3@3140,1200 v1(3210,1200)
J1-5: J1.5 | length 70
  L1_Analog w36: J1.5@3140,1100 v1(3210,1100)
J1-7: J1.7 | length 70
  L1_Analog w36: J1.7@3140,1000 v1(3210,1000)
J1-9: J1.9 | length 70
  L1_Analog w36: J1.9@3140,900 v1(3210,900)
J1-11: J1.11 | length 70
  L1_Analog w36: J1.11@3140,800 v1(3210,800)
J1-14: J1.14
J1-16: J1.16
J1-18: J1.18
J1-20: J1.20
J19_3: J19.3 | length 84.5
  L1_Analog w12.52: J19.3@3837.01,503.54 3916.46,503.54 v1(3920,500)
J19_7: J19.7 | length 79.5
  L1_Analog w12.52: J19.7@3837.01,566.54 v1(3916.54,566.54)
J19_9: J19.9
J19_15: J19.15 | length 90.2
  L1_Analog w12.52: J19.15@3837.01,692.52 3902.52,692.52 v1(3920,710)
J19_17: J19.17 | length 55.5
  L1_Analog w12.52: J19.17@3837.01,724.02 3884.02,724.02 v1(3890,730)
J19_18: J19.18 | length 64.7
  L1_Analog w12.52: v1(3700,720) 3704.02,724.02 J19.18@3762.99,724.02
J19_19: J19.19 | length 85.4
  L1_Analog w12.52: J19.19@3837.01,755.51 3878.55,755.51 3879.17,756.13 3900.83,756.13 3901.45,755.51 3915.51,755.51 v1(3920,760)
J19_20: J19.20 | length 96.2
  L1_Analog w12.52: v1(3670,760) 3674.49,755.51 3687.53,755.51 3689.17,753.87 3710.83,753.87 3712.47,755.51 J19.20@3762.99,755.51
J19_21: J19.21 | length 54.2
  L1_Analog w12.52: J19.21@3837.01,787.01 3887.01,787.01 v1(3890,790)
J19_22: J19.22 | length 64.2
  L1_Analog w12.52: v1(3700,790) 3702.99,787.01 J19.22@3762.99,787.01
J19_23: J19.23
J19_24: J19.24
J19_26: J19.26
J19_27: J19.27 | length 83.6
  L1_Analog w12.52: J19.27@3837.01,881.5 3918.5,881.5 v1(3920,880)
J19_28: J19.28
J19_31: J19.31
J19_36: J19.36 | length 45.9
  L1_Analog w12.52: v1(3721.87,1010) 3720,1010 3722.52,1007.48 J19.36@3762.99,1007.48
J19_37: J19.37
J19_40: J19.40
J19_41: J19.41
J19_43: J19.43
N18V: C48.2 C49.2 C50.2 C51.1 C52.2 C57.2 D4.2 J14.1 J17.1 R66.1 R68.1 U9.9 U9.11 | length 2225.1
  L1_Analog w11.81: C57.2@2900,422 C57.2@2902,420 2920.31,401.69 U9.9@2920.31,330.71 2920.31,269.68 U9.11@2940,250 2966.38,276.38 R66.1@3030,276.38
  L1_Analog w12.52: C57.2@2900,422 C52.2@2900,462 ; U9.11@2966.38,223.62 R68.1@3030,223.62 3035.62,218 C51.1@3080,218 3162,218 J17.1@3170,210
  L1_Analog w40: J14.1@2040,940 1970,870 1970,720 2087.09,602.91 C50.2@2330,602.91 C49.2@2460,602.91 2537.09,602.91 2580,560 2580,380 2638.74,321.26 D4.2@2700,321.26 2700,240 2720,220 v1(2750,220) 2780,250 U9.11@2916.38,250
  L6_Digital w50: v1(2750,220) 2800,170 C48.2@2847.64,170
  other v1: 2916.38,232.28 2963.62,232.28 2916.38,267.72 2963.62,267.72
NetC4_1: C4.1 R19.2 U1.1 | length 157.7
  L1_Analog w12.52: C4.1@2200,2140 2202.76,2142.76 U1.1@2272.6,2142.76 2272.6,2097.17 R19.2@2245.43,2070
NetC4_2: C4.2 R1.1 U1.4 | length 252
  L1_Analog w12.52: R1.1@2130,2213.62 2136.38,2220 2200,2220 2230,2190 2300.16,2190 U1.4@2347.4,2237.24
NetC8_2: C8.2 C9.2 U2.7 | length 197.4
  L1_Analog w11.81: U2.7@1919.06,1731.22 1919.06,1832.06 C9.2@1922,1835
  L1_Analog w25: C9.2@1922,1835 1922,1919.09 C8.2@1927.91,1925
NetC11_1: C11.1 R10.2 U2.10 | length 396.7
  L1_Analog w11.81: R10.2@1623.62,1540 1620,1543.62 C11.1@1620,1588.5 1798.5,1588.5 1860,1650 U2.10@1860,1731.22
NetC11_2: C11.2 R14.2 U2.11 | length 339
  L1_Analog w11.81: R14.2@1623.62,1700 1620,1696.38 C11.2@1620,1651.5 1821.5,1651.5 1840.32,1670.32 U2.11@1840.32,1731.22
NetC12_1: C12.1 R23.2 U2.12 | length 197.1
  L1_Analog w11.81: C12.1@1818,1880 1820.63,1877.37 U2.12@1820.63,1731.22
  L1_Analog w12.52: C12.1@1818,1880 1818,1924.38 R23.2@1820,1926.38
NetC12_2: C12.2 R25.2 U2.13 | length 212.1
  L1_Analog w11.81: C12.2@1762,1880 1762,1858 1800.94,1819.06 U2.13@1800.94,1731.22
  L1_Analog w12.52: R25.2@1760,1926.38 1762,1924.38 C12.2@1762,1880
NetC13_1: C13.1 R24.1 U2.27 | length 197.1
  L1_Analog w11.81: C13.1@1818,1360 1820.63,1362.63 U2.27@1820.63,1508.78
  L1_Analog w12.52: C13.1@1818,1360 1818,1315.62 R24.1@1820,1313.62
NetC13_2: C13.2 R26.1 U2.26 | length 212.1
  L1_Analog w11.81: C13.2@1762,1360 1770,1368 1770,1390 1800.94,1420.94 U2.26@1800.94,1508.78
  L1_Analog w12.52: R26.1@1760,1313.62 1762,1315.62 C13.2@1762,1360
NetC14_1: C14.1 R27.2 U2.14 | length 223.1
  L1_Analog w11.81: C14.1@1718,1880 1718,1869.09 1719.61,1869.09 1776.1,1812.6 1776.1,1811.6 1781.26,1806.44 1781.26,1798.74 U2.14@1781.26,1731.22
  L1_Analog w12.52: C14.1@1718,1880 1718,1924.38 R27.2@1720,1926.38
NetC14_2: C14.2 R29.2 U2.15 | length 261.2
  L1_Analog w11.81: C14.2@1662,1880 1662,1858 1670.59,1849.41 1711.45,1849.41 1756.41,1804.45 1756.41,1803.44 1761.57,1798.28 1761.57,1785.35 U2.15@1761.57,1731.22
  L1_Analog w12.52: R29.2@1660,1926.38 1662,1924.38 C14.2@1662,1880
NetC15_1: C15.1 R28.1 U2.25 | length 222.2
  L1_Analog w11.81: C15.1@1718,1360 1718,1368 1781.26,1431.26 U2.25@1781.26,1508.78
  L1_Analog w12.52: C15.1@1718,1360 1718,1315.62 R28.1@1720,1313.62
NetC15_2: C15.2 R30.1 U2.24 | length 260.7
  L1_Analog w11.81: C15.2@1662,1360 1662,1382 1670,1390 1710,1390 1761.57,1441.57 U2.24@1761.57,1508.78
  L1_Analog w12.52: R30.1@1660,1313.62 1662,1315.62 C15.2@1662,1360
NetC17_1: C17.1 J10.1 R33.2 U4.1 | length 645.1
  L6_Digital w12.52: C17.1@930,1702 930,1680 955,1655 957.33,1655 968.97,1643.37 991.03,1643.37 1002.67,1655 1041.5,1655 1041.5,1639.05 1140.23,1639.05 1142.19,1641.02 1152.57,1641.02 1163.62,1652.07 R33.2@1163.62,1710 1148.39,1725.24 U4.1@1148.39,1781.57 1221.57,1781.57 J10.1@1320,1880
NetC17_2: C17.2 R42.2 R43.1 | length 92.5
  L6_Digital w11.81: C17.2@930,1758 942,1770 R43.1@976.38,1770 973.62,1772.76 R42.2@973.62,1810
NetC18_1: C18.1 R32.1 U2.23 | length 283.6
  L1_Analog w11.81: C18.1@1618,1360 1618,1388 1645.28,1415.28 1707.3,1415.28 1741.89,1449.87 U2.23@1741.89,1508.78
  L1_Analog w12.52: C18.1@1618,1360 1618,1315.62 R32.1@1620,1313.62
NetC18_2: C18.2 R35.1 U2.22 | length 317.5
  L1_Analog w11.81: C18.2@1562,1360 1562,1392 1604.96,1434.96 1699.14,1434.96 1722.2,1458.02 U2.22@1722.2,1508.78
  L1_Analog w12.52: R35.1@1560,1313.62 1562,1315.62 C18.2@1562,1360
NetC19_1: C19.1 R31.2 U2.16 | length 290.1
  L1_Analog w11.81: C19.1@1618,1880 1618,1842 1630.28,1829.72 1703.3,1829.72 1736.73,1796.29 1736.73,1795.29 1741.89,1790.13 U2.16@1741.89,1731.22
  L1_Analog w12.52: C19.1@1618,1880 1618,1924.38 R31.2@1620,1926.38
NetC19_2: C19.2 R34.2 U2.17 | length 323.9
  L1_Analog w11.81: C19.2@1562,1880 1562,1838.04 1590,1810.04 1695.14,1810.04 1717.04,1788.14 1717.04,1787.14 1722.2,1781.98 U2.17@1722.2,1731.22
  L1_Analog w12.52: R34.2@1560,1926.38 1562,1924.38 C19.2@1562,1880
NetC20_1: C20.1 R37.2 U2.18 | length 340.7
  L1_Analog w11.81: 1696.75,1779.59 1702.52,1773.82 U2.18@1702.52,1731.22
  L1_Analog w12.52: R37.2@1520,1926.38 1518,1924.38 C20.1@1518,1880 1518,1842 1570,1790 1686.84,1790 1697,1779.84
NetC20_2: C20.2 R40.2 U2.19 | length 360.1
  L1_Analog w11.81: C20.2@1462,1880 1462,1828 1558.78,1731.22 U2.19@1682.83,1731.22
  L1_Analog w12.52: R40.2@1460,1926.38 1462,1924.38 C20.2@1462,1880
NetC21_1: C21.1 R38.1 U2.21 | length 334.7
  L1_Analog w11.81: C21.1@1518,1360 1518,1388 1584.65,1454.65 1690.99,1454.65 1702.52,1466.18 U2.21@1702.52,1508.78
  L1_Analog w12.52: C21.1@1518,1360 1518,1315.62 R38.1@1520,1313.62
NetC21_2: C21.2 R41.1 U2.20 | length 348.4
  L1_Analog w11.81: C21.2@1462,1360 1462,1392 1578.78,1508.78 U2.20@1682.83,1508.78
  L1_Analog w12.52: R41.1@1460,1313.62 1460,1358 C21.2@1462,1360
NetC22_1: C22.1 J8.1 R39.2 U4.7 | length 646.1
  L6_Digital w13.78: C22.1@930,2048 930,2070 996.57,2136.57 998.02,2136.57 998.71,2137.26 1047.67,2137.26 1048.36,2136.57 1105.67,2136.57 1123.62,2118.62 R39.2@1123.62,2050 ; U4.7@1122.8,1978.43 1122.8,2049.17 R39.2@1123.62,2050 ; J8.1@1320,2190 1180,2050 R39.2@1123.62,2050
NetC22_2: C22.2 R45.2 R46.1 | length 92.5
  L6_Digital w13.78: C22.2@930,1992 942,1980 R45.2@976.38,1980 973.62,1977.24 R46.1@973.62,1940
NetC23_1: C23.1 R22.2 R43.2 U4.3 | length 195.2
  L6_Digital w13.78: R22.2@1023.62,1690 C23.1@1023.62,1730 ; R43.2@1023.62,1770 C23.1@1023.62,1730 ; U4.3@1097.2,1781.57 1097.2,1747.02 1080.58,1730.39 1024.01,1730.39 C23.1@1023.62,1730
NetC25_1: C25.1 R45.1 R76.2 U4.5 | length 128.6
  L6_Digital w13.78: R76.2@1023.62,2060 C25.1@1023.62,2020 R45.1@1023.62,1980 1025.2,1978.43 U4.5@1071.61,1978.43
NetC27_1: C27.1 J9.3 R47.2 U5.1 | length 604
  L6_Digital w12.52: C27.1@930,1192 930,1170 970,1130 1131.17,1130 1163.62,1162.46 ; U5.1@1148.39,1271.57 1148.39,1215.24 R47.2@1163.62,1200
  L6_Digital w13.78: R47.2@1163.62,1200 1163.62,1162.46 1207.54,1162.46 J9.3@1320,1050
NetC27_2: C27.2 R50.2 R51.1 | length 92.5
  L6_Digital w11.81: C27.2@930,1248 942,1260 R51.1@976.38,1260 973.62,1262.76 R50.2@973.62,1300
NetC28_1: C28.1 J11.3 R49.2 U5.7 | length 672.2
  L6_Digital w13.78: C28.1@930,1538 930,1560 990,1620 1030.82,1620 1032.79,1618.03 1111.97,1618.03 1122.8,1607.2 U5.7@1122.8,1468.43 ; R49.2@1123.62,1540 1170,1540 1280,1430 1280,1400 J11.3@1320,1360
NetC28_2: C28.2 R53.2 R54.1 | length 92.5
  L6_Digital w13.78: C28.2@930,1482 942,1470 R53.2@976.38,1470 973.62,1467.24 R54.1@973.62,1430
NetC29_1: C29.1 R51.2 R74.2 U5.3 | length 195.2
  L6_Digital w13.78: R74.2@1023.62,1180 C29.1@1023.62,1220 ; R51.2@1023.62,1260 C29.1@1023.62,1220 ; U5.3@1097.2,1271.57 1097.2,1237.02 1080.58,1220.39 1024.01,1220.39 C29.1@1023.62,1220
NetC31_1: C31.1 R21.2 R53.1 U5.5 | length 128.6
  L6_Digital w13.78: R21.2@1023.62,1550 C31.1@1023.62,1510 R53.1@1023.62,1470 1025.2,1468.43 U5.5@1071.61,1468.43
NetC34_1: C34.1 J13.2 R58.2 U6.8 | length 772.2
  L6_Digital w17.72: C34.1@1377.09,440 1374.65,442.44 U6.8@1374.65,541.61 1457.99,541.61 R58.2@1466.38,550
  L6_Digital w25: C34.1@1377.09,440 1620,440 1720,540 J13.2@1720,730
NetC37_1: C37.1 J12.2 R60.2 U7.8 | length 2538.3
  L3_AnalogPower w40: J12.2@1320,730 1320,770 1360,810 1800,810 2100,1110 2680,1110 3100,1530 v1(3100,1660)
  L6_Digital w17.72: U7.8@2852.36,1667.99 2891.37,1667.99 2908.1,1651.27 2908.73,1651.27 2920,1640 2940.47,1640 R60.2@2947.72,1632.76 2982.76,1632.76 3009.29,1659.29 C37.1@3037.72,1659.29 3099.29,1659.29 v1(3100,1660)
NetC38_2: C38.2 R55.1 R57.1 U6.2 | length 212.1
  L6_Digital w17.72: R55.1@1103.62,610 1110,616.38 R57.1@1110,666.38 ; R55.1@1111.5,602.13 1111.5,550 1140,550 1157.2,567.2 U6.2@1205.35,567.2
NetC39_2: C39.2 R56.1 R59.2 U7.2 | length 221.8
  L6_Digital w17.72: R59.2@2583.62,1760 2587.72,1755.91 2587.72,1697.87 2592.01,1693.58 U7.2@2683.07,1693.58
  L6_Digital w25: R56.1@2527.72,1700 2585.59,1700 C39.2@2587.72,1697.87
NetC40_1: C40.1 U6.6 | length 96.8
  L6_Digital w17.72: U6.6@1374.65,592.8 1461.3,592.8 C40.1@1468.5,600
NetC41_1: C41.1 U7.6 | length 101.9
  L6_Digital w17.72: U7.6@2852.36,1719.17 2899.17,1719.17 2914.88,1734.88 C41.1@2947.72,1734.88
NetC42_1: C42.1 U8.6 | length 90.3
  L6_Digital w17.72: U8.6@2212,483 2294.5,483 C42.1@2300,488.5
NetC42_2: C42.2 U8.4 | length 90.3
  L6_Digital w17.72: U8.4@2212,557 2294.5,557 C42.2@2300,551.5
NetC45_1: C45.1 D4.1 L1.1 U9.10 | length 889.6
  L1_Analog w11.81: D4.1@2700,478.74 2700,420 2730,390 2870,390 2900.63,359.37 U9.10@2900.63,330.71 2840.71,330.71 v1(2820,310)
  L1_Analog w12.52: v1(2750,150) 2770,170 C45.1@2802,170
  L1_Analog w20: D4.1@2700,478.74 2751.1,529.84 L1.1@2751.1,641.34
  L6_Digital w12.52: v1(2750,150) 2710.24,189.76 2710.24,236.47 2783.77,310 v1(2820,310)
NetC45_2: C45.2 U9.1 | length 39.4
  L1_Analog w11.81: C45.2@2861.5,170 2862.2,169.29 U9.1@2900.63,169.29
NetC46_1: C46.1 C47.1 C48.1 D3.1 D9.3 D10.3 R63.1 U8.5 U9.2 | length 2496.2
  L1_Analog w11.81: v1(2907.01,80) 2920.31,93.3 U9.2@2920.31,169.29
  L3_AnalogPower w40: v1(2490,480) v1(2490,450) 2490,200 ; v1(2940,80) v1(2907.01,80) 2760,80 2640,200 2490,200 ; v1(2180,200) 2490,200 ; v1(2180,200) v1(2180,240) v1(2140,240) v1(2140,200) v1(2180,200)
  L6_Digital w20: D10.3@2060,357.4 D9.3@2060,197.4 2137.4,197.4 v1(2140,200)
  L6_Digital w24: R63.1@2153.62,610 2170,593.62 ; U8.5@2212,520 2180,520 2170,530 2170,593.62 ; D3.1@2414.47,650 2380,615.53 C47.1@2380,560 ; v1(2490,450) v1(2490,480) 2490,490 2420,560 C47.1@2380,560 ; 2170,593.62 2170,610 2208,610 C46.1@2220,622 2220,618.5 2238.5,600 2340,600 C47.1@2380,560
  L6_Digital w40: v1(2907.01,80) 3052.36,80 C48.1@3052.36,170
NetC51_2: C51.2 U9.4 | length 203.8
  L1_Analog w11.81: U9.4@2959.69,169.29 2959.69,130.31 2975,115 3065,115 3080,130 C51.2@3080,162
NetC52_1: C52.1 R70.1 | length 61.8
  L1_Analog w12.52: C52.1@2900,518 2955.62,518 R70.1@2960,513.62
NetC54_1: C54.1 J14.2 R72.2 U10.8 | length 1703.2
  L3_AnalogPower w40: J14.2@2040,840 2060.35,819.65 2243.26,819.65 2463.61,1040 2680,1040 2690,1050 2701.8,1050 2736.18,1084.38 2815.62,1163.82 3046.18,1394.38 3059.83,1394.38 3086.18,1394.38 3125.9,1434.1 v1(3130,1430)
  L6_Digital w17.72: U10.8@2852.36,1447.99 2892.01,1447.99 2910,1430 2910,1420 2917.24,1412.76 R72.2@2947.72,1412.76 3022.76,1412.76 3037.72,1427.72 C54.1@3037.72,1459.29 3099.29,1459.29 3100,1460 v1(3130,1430)
NetC56_2: C56.2 R71.1 R73.2 U10.2 | length 230.1
  L6_Digital w17.72: R71.1@2527.72,1500 2529.84,1497.87 C56.2@2587.72,1497.87 ; R73.2@2583.62,1560 2587.72,1555.91 C56.2@2587.72,1497.87 ; U10.2@2683.07,1473.58 2636.42,1473.58 2612.13,1497.87 C56.2@2587.72,1497.87
NetC57_1: C57.1 R70.2 U9.8 | length 144
  L1_Analog w11.81: U9.8@2940,330.71 2940,402 C57.1@2958,420 C57.1@2960,422
  L1_Analog w12.52: C57.1@2960,422 R70.2@2960,466.38
NetC58_1: C58.1 U10.6 | length 101.9
  L6_Digital w17.72: U10.6@2852.36,1499.17 2909.17,1499.17 2924.88,1514.88 C58.1@2947.72,1514.88
NetD1_2: D1.2 R12.1 | length 187.4
  L1_Analog w25: D1.2@2045,1210 v1(2090,1210)
  L6_Digital w25: R12.1@2040,1100 2040,1180 2070,1210 v1(2090,1210)
NetD2_2: D2.2 L1.4 | length 460.2
  L1_Analog w40: 2400,1070.55 2420,1090.55 2420,1120 2440,1140 D2.2@2508.74,1140 2600,1140 2620,1120 2740,1120 2751.1,1108.9 L1.4@2751.1,1058.66
NetD10_1: D10.1 R105.2 | length 2420.9
  L3_AnalogPower w40: v1(2100,345) v1(2100,380) v1(2100,420) 2220,540 2750,540 3019.65,270.35 3450.35,270.35 3610,430 3610,695 3585,720 v1(3585,725) v1(3585,755) v1(3620,755) v1(3620,725)
  L6_Digital w19.68: R105.2@3606.38,660 3606.38,706.38 3620,720 v1(3620,725)
  L6_Digital w24: D10.1@2097.4,282.6 v1@2097.4,345 ; v1(2100,345) v1(2100,380) v1(2100,420)
NetD10_2: D10.2 R61.1 | length 2453.7
  L3_AnalogPower w40: v1(2020,345) v1(2020,380) v1(2020,420) 2190,590 3040,590 3050,600 3050,1280 3115.87,1345.87 3229,1345.87 3255.87,1319 3255.87,1270.87 3239.13,1254.13 3184.13,1254.13 v1(3180,1250) v1(3150,1250)
  L6_Digital w20: v1(2020,345) v1(2020,380) v1(2020,420) ; D10.2@2022.6,282.6 v1@2022.6,345 ; R61.1@3226.38,1260 3240,1273.62 3240,1290 v1(3250,1300)
NetJ1_6: J1.6 R6.2 | length 116.8
  L1_Analog w12.52: v1(3290,1100) J1.6@3360,1100
  L6_Digital w12.52: R6.2@3273.62,1140 3273.62,1116.38 v1(3290,1100)
NetJ1_8: J1.8 R7.2 | length 116.8
  L1_Analog w12.52: v1(3290,1000) J1.8@3360,1000
  L6_Digital w12.52: R7.2@3273.62,1040 3273.62,1016.38 v1(3290,1000)
NetJ1_10: J1.10 R4.2 | length 116.8
  L1_Analog w12.52: v1(3290,900) J1.10@3360,900
  L6_Digital w12.52: R4.2@3273.62,940 3273.62,916.38 v1(3290,900)
NetJ1_12: J1.12 R5.2 | length 116.8
  L1_Analog w12.52: v1(3290,800) J1.12@3360,800
  L6_Digital w12.52: R5.2@3273.62,840 3273.62,816.38 v1(3290,800)
NetJ1_13: J1.13 R2.2 | length 132.6
  L1_Analog w12.52: J1.13@3130,700 J1.13@3140,700 v1(3210,700)
  L6_Digital w12.52: v1(3210,700) 3230,700 3236.38,706.38 R2.2@3236.38,730
NetJ1_15: J1.15 R3.2 | length 122.6
  L1_Analog w12.52: J1.15@3140,600 v1(3210,600)
  L6_Digital w12.52: v1(3210,600) 3230,600 3236.38,606.38 R3.2@3236.38,630
NetJ1_17: J1.17 R8.2 | length 122.6
  L1_Analog w12.52: J1.17@3140,500 v1(3210,500)
  L6_Digital w12.52: v1(3210,500) 3230,500 3236.38,506.38 R8.2@3236.38,530
NetJ1_19: J1.19 R9.2 | length 122.6
  L1_Analog w12.52: J1.19@3140,400 v1(3210,400)
  L6_Digital w12.52: v1(3210,400) 3230,400 3236.38,406.38 R9.2@3236.38,430
NetJ8_2: J8.2 R31.1 | length 359.4
  L1_Analog w12.52: J8.2@1320,2090 1488.58,2090 cw(c1488.58,1990) 1559.29,2060.71 1620,2000 R31.1@1620,1973.62
NetJ9_2: J9.2 R32.2 | length 371.1
  L1_Analog w12.52: J9.2@1320,1150 1508.58,1150 ccw(c1508.58,1250) 1579.29,1179.29 1620,1220 R32.2@1620,1266.38
NetJ10_2: J10.2 R37.1 | length 413.9
  L1_Analog w12.52: J10.2@1320,1780 1321.72,1780 ccw(c1321.72,1848.28) 1370,1800 ccw(c1345.86,1824.14) 1380,1824.14 1380,1923.69 cw(c1446.31,1923.69) 1399.39,1970.55 ; 1399.42,1970.58 1399.99,1970.58 1434.93,2005.52 1514.47,2005.52 1520,2000 R37.1@1520,1973.62 1520,1990
NetJ11_2: J11.2 R38.2 | length 397.5
  L1_Analog w12.52: J11.2@1320,1460 1350,1430 cw(c1301.72,1381.72) 1370,1381.72 1370,1315.36 ccw(c1455.36,1315.36) 1394.96,1255.04 ccw(c1455.36,1315.36) 1395,1255 ccw(c1455.36,1315.36) 1395.04,1254.96 ccw(c1455.36,1315.36) 1455.36,1230 1520,1230 R38.2@1520,1266.38
NetJ15_2: J15.2 R50.1 | length 162.3
  L6_Digital w12.52: J15.2@830,1420 830,1396.38 873.37,1353.01 873.37,1348.97 888.97,1333.37 893.01,1333.37 R50.1@926.38,1300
